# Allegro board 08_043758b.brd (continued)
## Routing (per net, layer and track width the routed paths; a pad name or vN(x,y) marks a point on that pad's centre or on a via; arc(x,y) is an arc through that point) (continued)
UNNAMED_9_RES_I270_N1: length 3.8
  BOTTOM w0.305: Q2.1 111.05,116.33 112.03,117.31 R66.2 R67.1
UNNAMED_11_ICUSB3320C_I29_RBIAS: length 1.6
  TOP w0.127: v1(87.54,100.2) U15.24
  BOTTOM w0.127: v1(87.54,100.2) 87.54,99.69 R77.1
UNNAMED_11_ICUSB3320C_I29_REFCL: length 2.2
  TOP w0.254: U15.26 86.34,101.28 R82.1
UNNAMED_11_RES_I67_N2: length 1.5
  TOP w0.305: Y1.3 87,104.35 R82.2
USB_ID: length 30.8
  TOP w0.127: U15.23 88.73,98.86 90.31,100.44 v1(90.31,100.95) ; P2.4 v1(112.41,105.9)
  L5_SIG w0.127: v1(112.41,105.9) 111.65,106.66 101.74,106.66 100.98,105.9 100.98,104.38 98.19,101.58 90.95,101.58 v1(90.31,100.95)
USB_OTG_CPEN: length 42.5
  TOP w0.127: v1(108.73,116.44) 109.41,115.77 U16.B1 ; v1(89.3,94.85) 87.9,94.85 87.54,95.21 U15.17
  L5_SIG w0.127: v1(89.3,94.85) 89.3,96.12 89.81,96.63 89.81,100.19 89.55,100.44 89.55,101.46 90.06,101.96 98.03,101.96 100.6,104.54 100.6,106.06 101.59,107.04 103.23,107.04 105.35,109.17 105.35,115.52 106.28,116.44 v1(108.73,116.44)
USB_OTG_N: length 24.6
  TOP w0.102: L6.4 107.68,103.35 107.95,103.08 107.95,101.66 105.56,99.27 94.12,99.27 91.6,96.75 87.96,96.75 87.85,96.86 U15.19
USB_OTG_P: length 25
  TOP w0.102: L6.1 108.48,103.35 108.21,103.08 108.21,101.55 105.67,99.01 94.23,99.01 91.71,96.48 87.95,96.48 87.83,96.36 U15.18
USB_VBUS_OTG: length 32.5
  TOP w0.254: v1(91.46,100.95) 89.04,98.54 88.28,98.54 88.11,98.36 U15.22
  L5_SIG w0.508: v1(91.46,100.95) 98.44,100.95 102,104.5 v1(102,105.52) v1(102.76,105.52)
  BOTTOM w0.508: v1(102,105.52) v1(102.76,105.52) 102.76,108.48 105.41,111.13 109.39,111.13 110.34,112.09 R88.2
USR_BTN: length 67.2
  TOP w0.127: U4.B9 68.07,104.03 71.87,104.03 72.37,103.53 77.48,103.53 78.79,102.22 79.14,102.22 79.52,102.6 79.52,103.16 79.77,103.41 81.85,103.41 83.58,105.14 83.58,107.3 86.25,109.97 v1(88.03,109.97)
  TOP w0.203: v1(114.35,94.56) S1.1
  L6_SIG w0.127: v1(88.03,109.97) 91.02,109.97 94.36,106.63 94.36,100.15 97.92,96.59 97.92,95.07 98.3,94.69 99.19,94.69 100.71,93.16 108.72,93.16 109.22,93.67 113.46,93.67 v1(114.35,94.56)
  BOTTOM w0.203: R57.2 88.41,109.58 v1(88.03,109.97)
USR_LED: length 57.8
  TOP w0.102: U4.D10 v2(66.47,103.23)
  TOP w0.127: Q4.1 111.69,84.86 R75.1 v1(109.22,84.86)
  L6_SIG w0.127: v1(109.22,84.86) 99.11,84.86 93.98,89.99 93.98,94.61 87.27,101.33 86.88,101.33 84.98,103.23 82.69,103.23 81.29,101.83 78.58,101.83 78.08,102.33 77.28,102.33 76.38,103.23 76.38,103.23 67.88,103.23 67.47,102.82 66.87,102.82 v2(66.47,103.23)
VTT_0P75: length 29.8
  TOP w0.203: 48.52,124.91 U14.3
  TOP w0.889: 49.66,125.55 C79.1 50.51,126.35
  BOTTOM w0.305: R22.2 R29.2 ; R22.2 54.73,123.75 ; R22.2 55.14,124.21 ; R29.2 55.14,122.15 R18.2 ; R29.2 54.73,122.95 ; 60.03,125.15 R37.2 R31.2 ; R23.2 59.66,129.38 ; R23.2 R24.2 58.86,129.38 ; R23.2 R16.2 ; 54.63,126.76 R17.2 ; R17.2 R26.2 54.63,127.56 ; R17.2 R34.2 ; R18.2 R27.2 ; R18.2 54.73,122.15 ; R27.2 55.14,120.89 ; R27.2 54.73,121.35 ; 55.14,119.69 R20.2 ; R20.2 55.14,120.61 ; R20.2 54.73,120.15 ; R16.2 60.46,129.38 ; R16.2 R35.2 ; R39.2 R33.2 ; R39.2 62.06,129.38 ; R39.2 R35.2 ; R33.2 62.86,129.38 ; R33.2 63.32,128.97 ; 52.95,128.93 C101.1 ; C101.1 52.95,130.05 ; C101.1 53.51,129.49 ; 50.79,126.26 R43.1 51.35,126.82 ; 58.5,119.13 R28.2 ; R28.2 R30.2 ; R28.2 58.96,118.72 ; 54.63,125.95 R34.2 ; R34.2 55.04,125.49 ; R21.2 R30.2 ; R21.2 60.56,118.72 ; R21.2 R38.2 ; R30.2 59.76,118.72 ; 57.46,118.72 R19.2 ; R19.2 57.91,119.13 ; R19.2 57,119.13 ; R25.2 56.66,129.38 ; R35.2 61.26,129.38 ; 60.03,124.35 R32.2 ; 60.03,123.55 R36.2
  vias: v1(51.06,125.93) v1(51.06,125.17) v1(51.82,125.93) v1(51.82,125.17)
VTTVREF: length 79.7
  TOP w0.152: 60.56,123.05 v2(60.56,122.15)
  TOP w0.203: U14.6 45.19,125.71 45.05,125.86 44.06,125.86 C84.1
  TOP w0.305: U4.F4 v2(64.87,108.83) ; U2.M8 v2(60.56,122.15) ; U2.H1 v2(63.76,127.75)
  TOP w0.508: 54.36,130.5 54.36,125.65 55.46,124.55 59.66,124.55 60.56,123.65 60.56,123.05 ; 54.36,130.5 45.59,130.5 44.77,129.68 C81.1 43.95,126.88 C84.1 ; 54.36,130.5 56.9,130.5 57.79,129.61 62.23,129.61 63.12,130.5 v1(63.76,130.5) v2(63.76,127.75)
  BOTTOM w0.152: 65.26,109.22 65.26,110.04 64.86,110.44 64.46,110.04 64.46,109.24 64.87,108.84 v2(64.87,108.83) 65.26,109.22
  BOTTOM w0.305: C63.2 64.25,127.75 v2(63.76,127.75) ; v2(60.56,122.15) 61.04,121.66 C102.1 ; 66.46,112.14 C99.2
  BOTTOM w0.508: 64.86,110.44 65.06,110.64 65.06,111.54 65.66,112.14 66.46,112.14 66.46,112.25 71.87,117.66 71.87,128.66 71.07,129.46 66.07,129.46 65.03,130.5 v1(63.76,130.5)

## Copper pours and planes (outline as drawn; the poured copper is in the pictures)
1V8 on TOP (solid shape): 47.15,82.47 47.34,82.47 47.44,82.43 47.54,82.41 48.23,82.41 48.28,82.41 48.33,82.42 48.39,82.42 48.39,82.37 48.45,82.37 48.45,82.31 48.43,82.26 48.43,82.21 48.43,81.52 48.44,81.45 48.47,81.36 48.47,81.1 50.3,81.1 50.3,80.85 50.28,80.85 50.28,80.81 50.22,80.74 49.75,80.74 49.75,79.93 50.22,79.93 50.28,79.86 50.28,79.83 50.3,79.83 50.3,78.56 47.88,78.56 46.1,80.34 46.1,83.26 47.15,83.26
1V8 on TOP (solid shape): 25.56,82.52 25.69,82.52 25.81,82.44 25.95,82.41 26.64,82.41 26.69,82.41 26.74,82.42 26.8,82.42 26.8,82.37 26.86,82.37 26.86,82.31 26.84,82.26 26.84,82.21 26.84,81.52 26.85,81.45 26.88,81.36 26.88,81.1 28.4,81.1 28.4,81.15 28.52,81.14 28.59,81.15 28.67,81.12 28.71,81.05 28.71,80.85 28.69,80.85 28.69,80.81 28.63,80.74 28.16,80.74 28.16,79.93 28.63,79.93 28.69,79.86 28.69,79.83 28.71,79.83 28.71,78.56 27.05,78.56 24.51,81.1 24.51,83.26 25.56,83.26
1V8 on TOP: 47.88,123.01 47.88,116.02 50.3,116.02 50.3,123.01
1V8 on TOP: 93.48,108.4 89.67,108.4 89.67,102.56 93.98,102.56 93.98,107.9
1V8 on TOP: 43.18,84.91 39.88,84.91 39.88,83.39 40.39,82.88 40.39,80.97 43.18,80.97
1V8 on BOTTOM: 74.81,98.75 72.14,98.75 72.14,104.98 74.81,104.98
1V8 on BOTTOM: 91.2,102.56 93.73,102.56 93.73,107.26 91.2,107.26
1V8 on L8_PWR: 68.2,77.1 68.2,83.13 56.32,83.13 51.24,78.05 26.29,78.05 26.29,85.04 29.28,85.04 30.23,85.99 45.34,85.99 45.34,93.29 47.88,93.29 47.88,121.87 92.97,121.87 92.97,87.89 106.3,87.89 106.3,77.1
1V35 on TOP: 64.27,113.85 64.27,116.05 66.86,116.05 66.86,113.85
1V35 on TOP: 76.08,124.66 72.27,124.66 72.27,127.2 76.08,127.2
1V35 on TOP: 89.79,117.17 89.79,124.03 88.9,124.91 88.9,127.71 92.97,127.71 92.97,117.17 ; 1 cut-out
1V35 on L3_PWR: 54.68,105.67 47.25,113.11 47.25,131.39 59.47,131.39 60.82,131.14 62.17,131.39 85.67,131.39 85.67,128.22 92.02,128.22 92.02,112.98 86.94,112.98 86.94,107.26 66.11,107.26 64.21,109.17 59.63,109.17 59.63,105.67
GND on TOP: 88.14,115.52 88.14,116.66 97.67,116.66 98.05,117.04 98.94,117.04 98.94,117.8 102.24,117.8 102.24,114.63 98.94,114.63 98.94,115.26 97.79,115.26 97.73,115.33 98.79,115.33 98.79,115.74 97.47,115.74 97.47,115.52 ; 2 cut-outs
GND on TOP: outline of 86 points within 9.18,72.52 117.04,140.58 ; 52 cut-outs
GND on BOTTOM: 112.62,76.18 88.68,73.51 64.62,72.52 64.62,78.16 60.82,81.96 57.02,78.16 57.02,75.77 41.53,75.77 41.53,73.15 28.69,74.18 15.88,75.68 12.53,76.16 9.18,76.66 9.18,136.43 10.24,136.6 10.24,136.6 25.22,138.56 40.26,139.87 40.26,139.86 57.02,139.86 57.02,134.94 57.14,134 57.48,133.12 57.48,131.77 58.32,131.77 58.32,132.08 59.94,131.25 61.75,131.26 61.75,130.83 63.55,130.83 63.55,131.04 64.19,131.04 64.19,133.19 64.51,134.04 64.62,134.94 64.62,140.58 85.82,139.8 106.94,137.71 106.94,112.98 103.45,109.48 103.45,107.58 104.08,108.21 110.75,108.21 111.07,107.9 111.07,101.23 117.02,101.23 117.02,98.8 117.04,98.8 117.04,87.4 117.04,81.96 117.04,80.49 116.03,77.75 113.49,76.32 ; 73 cut-outs
GND on L2_GND: 112.62,76.18 88.68,73.51 64.62,72.52 64.62,78.16 60.82,81.96 57.02,78.16 57.02,72.56 33.03,73.78 9.18,76.66 9.18,136.43 33.03,139.32 57.02,140.54 57.02,134.94 60.82,131.14 64.62,134.94 64.62,140.58 85.82,139.8 106.94,137.71 106.94,113.11 105.67,111.84 105.67,108.21 113.47,108.21 113.61,108.08 113.61,105.99 111.07,105.99 111.07,101.23 117.04,101.23 117.04,81.96 117.04,80.49 116.03,77.75 113.49,76.32
GND on L3_PWR: 112.62,76.18 88.68,73.51 64.62,72.52 64.62,78.16 60.82,81.96 57.02,78.16 57.02,72.56 33.03,73.78 9.18,76.66 9.18,136.43 33.03,139.32 57.02,140.54 57.02,134.94 57.38,133.33 58.38,132.03 46.61,132.03 46.61,123.14 32.01,123.14 32.01,115.38 34.42,112.98 39.5,112.98 44.07,108.4 44.07,95.2 40.58,95.2 40.58,82.05 40.77,81.86 54.87,81.86 54.87,89.16 59,89.16 59,82.5 63.31,82.5 65.85,79.96 117.01,79.96 115.86,77.55 113.49,76.32
GND on L4_GND, L7_GND, L9_GND: 112.62,76.18 88.68,73.51 64.62,72.52 64.62,78.16 60.82,81.96 57.02,78.16 57.02,72.56 33.03,73.78 9.18,76.66 9.18,136.43 33.03,139.32 57.02,140.54 57.02,134.94 60.82,131.14 64.62,134.94 64.62,140.58 85.82,139.8 106.94,137.71 106.94,113.11 105.67,111.84 105.67,108.21 111.07,108.21 111.07,101.23 117.04,101.23 117.04,81.96 117.04,80.49 116.03,77.75 113.49,76.32
GND on L5_SIG: 112.62,76.18 88.68,73.51 64.62,72.52 64.62,78.16 60.82,81.96 57.02,78.16 57.02,72.56 33.03,73.78 9.18,76.66 9.18,136.43 33.03,139.32 57.02,140.54 57.02,134.94 60.82,131.14 64.62,134.94 64.62,140.58 85.82,139.8 106.94,137.71 106.94,116.14 105.9,116.14 105.9,111.94 105.67,111.71 105.67,109.48 104.08,107.9 104.08,106.94 111.07,106.94 111.07,101.23 117.04,101.23 117.04,87.4 117.04,80.49 116.03,77.75 113.49,76.32 ; 45 cut-outs
GND on L6_SIG: 112.62,76.18 88.68,73.51 64.62,72.52 64.62,78.16 60.82,81.96 57.02,78.16 57.02,72.56 33.03,73.78 9.18,76.66 9.18,136.43 33.03,139.32 57.02,140.54 57.02,134.94 60.82,131.14 64.62,134.94 64.62,140.58 85.82,139.8 106.94,137.71 106.94,112.98 105.67,111.71 105.67,108.21 110.75,108.21 111.07,107.9 111.07,101.23 117.04,101.23 117.04,87.4 117.04,80.49 116.03,77.75 113.49,76.32 ; 27 cut-outs
GND on L8_PWR: 112.62,76.18 88.68,73.51 64.62,72.52 64.62,78.16 60.82,81.96 57.02,78.16 57.02,72.56 33.03,73.78 9.18,76.66 9.18,136.43 33.03,139.32 57.02,140.54 57.02,134.94 57.21,133.74 57.78,132.66 42.8,132.66 42.8,131.71 19.31,131.71 19.31,85.04 25.66,85.04 25.66,77.42 51.51,77.42 56.59,82.5 67.57,82.5 67.57,76.46 106.94,76.46 106.94,88.53 93.6,88.53 93.6,132.66 63.86,132.66 64.42,133.74 64.62,134.94 64.62,140.58 85.82,139.8 106.94,137.71 106.94,113.11 105.67,111.84 105.67,108.21 111.07,108.21 111.07,101.23 117.04,101.23 117.04,80.49 116.03,77.75 113.49,76.32
GND on L8_PWR: 28.83,93.93 28.83,112.34 44.07,112.34 44.07,120.6 47.25,120.6 47.25,93.93 44.84,93.93 38.49,100.28 35.82,100.28 35.82,93.93
PGND on TOP: 114.3,113.99 115.7,113.99 115.7,116.91 114.3,116.91
PGND on TOP: 111.26,121.36 111.26,117.17 109.6,117.17 109.6,121.36
PGND on TOP: 107.57,127.45 112.27,127.45 112.27,129.36 107.57,129.36
PGND on TOP: 111.64,114.75 111.64,115.39 109.99,115.39 109.99,110.82 111.38,110.82 111.38,114.5
PGND on L2_GND, L3_PWR, L4_GND, L7_GND, L9_GND: 111.7,101.86 111.7,105.36 114.24,105.36 114.24,108.35 113.74,108.85 106.3,108.85 106.3,111.57 107.57,112.84 107.57,137.63 110.1,137.29 112.62,136.92 113.49,136.78 116.03,135.35 117.04,132.61 117.04,129.35 117.04,127.77 116.1,127.77 115.35,127.46 115.04,126.71 115.35,125.95 116.1,125.64 117.04,125.64 117.04,123.02 116.1,123.02 115.35,122.71 115.04,121.95 115.35,121.2 116.1,120.89 117.04,120.89 117.04,109.99 116.1,109.99 115.35,109.68 115.04,108.93 115.35,108.17 116.1,107.86 117.04,107.86 117.04,105.24 116.1,105.24 115.35,104.93 115.04,104.17 115.35,103.42 116.1,103.11 117.04,103.11 117.04,101.86
PGND on L5_SIG, L6_SIG: 106.3,108.85 106.3,111.39 107.57,112.66 107.57,133.17 115.04,133.17 115.04,119.16 115.83,118.37 115.83,112.02 115.04,111.24 115.04,108.43 115.38,108.09 115.38,105.04 115.04,104.7 115.04,101.86 111.7,101.86 111.7,105.04 112.02,105.36 114.24,105.36 114.24,108.21 113.61,108.85
VCCPINT on TOP: 85.35,84.91 95.38,84.91 95.38,90.12 85.35,90.12
VCCPINT on TOP: 64.57,93.62 72.72,93.62 72.72,95.97 64.57,95.97
VCCPINT on L3_PWR: 77.09,86.94 77.09,89.8 54.87,89.8 54.87,105.04 60.27,105.04 60.27,108.53 63.94,108.53 65.85,106.63 86.94,106.63 86.94,95.83 92.33,95.83 92.33,86.94
VDD_INTERFACE on TOP: 40.52,85.54 40.52,89.1 40.64,89.23 40.64,89.85 43.18,89.85 43.18,85.54
VDD_INTERFACE on L8_PWR: 36.45,86.62 36.45,99.64 38.23,99.64 44.58,93.29 44.71,93.29 44.71,86.62
VIN on TOP: 99.32,87.83 99.32,89.35 99.19,89.48 99.19,89.79 99.57,89.79 99.62,89.84 99.62,90.24 99.42,90.24 99.19,90.01 99.19,91.01 99.83,91.01 99.83,91.64 102.62,91.64 104.14,90.12 104.14,87.83 ; 1 cut-out
VIN on TOP: 59.06,83.39 61.85,83.39 61.85,85.93 59.31,85.93 59.06,85.67
VIN on TOP: 45.6,123.64 45.6,124.28 44.45,124.28 43.95,123.77 43.95,121.87 45.09,121.87 45.47,122.25 45.47,123.52 ; 1 cut-out
VIN on TOP: 100.46,118.12 98.87,118.12 98.05,118.95 98.05,124.41 100.21,124.41 100.46,124.15 ; 1 cut-out
VIN on TOP: 100.59,111.83 100.59,107.64 98.43,107.64 98.43,112.09 97.92,112.6 97.92,113.23 98.94,114.25 99.95,114.25 99.95,112.47 ; 1 cut-out
VIN on TOP: 88.27,129.23 88.27,131.9 93.35,131.9 93.35,131.39 95.25,131.39 95.63,131.01 95.63,129.23
VIN on L3_PWR: 66.11,80.59 63.57,83.13 59.63,83.13 59.63,89.16 76.46,89.16 76.46,86.31 92.97,86.31 92.97,96.47 87.57,96.47 87.57,112.34 92.65,112.34 92.65,128.85 86.3,128.85 86.3,139.76 96.63,138.89 106.94,137.71 106.94,113.11 105.67,111.84 105.67,108.21 111.07,108.21 111.07,101.23 117.04,101.23 117.04,80.59
VIN on L8_PWR: 43.44,121.23 43.44,132.03 58.38,132.03 60.82,131.14 63.25,132.03 92.97,132.03 92.97,122.5 47.25,122.5 47.25,121.23
VIN_5V_USB on TOP: 108.97,124.79 108.72,125.04 108.72,126.69 110.11,126.69 110.62,126.18 110.62,125.92 110.1,125.92 110.1,124.8 110.62,124.8 110.62,124.79
VIN_5V_USB on TOP: 108.21,110.82 108.21,110.85 108.84,110.85 108.84,111.26 108.21,111.26 108.21,113.36 109.48,113.36 109.48,110.94 109.35,110.82
VIN_5V_USB on TOP: 107.57,130.5 111.51,130.5 111.51,133.17 107.57,133.17
VIN_5V_USB on L8_PWR: 107.57,111.39 107.57,137.63 109.8,137.33 112.02,137.01 112.02,127.58 110.43,127.58 110.43,111.39
VIN_5V_USB_DATA on TOP: 108.21,108.91 108.21,110.07 109.18,110.07 109.18,110.15 109.19,110.15 109.19,110.55 108.21,110.55 108.21,110.56 109.35,110.56 109.86,110.06 110.87,110.06 112.34,108.59 112.34,108.02 111.89,108.02 111,108.91
VIN_5V_USB_DATA on BOTTOM: 108.21,110.44 111,110.44 111,108.85 108.21,108.85
VIN_5V_USB_POWER on TOP: 110.75,124.79 113.78,124.79 113.78,125.82 112.76,125.82 112.51,126.07 112.51,126.69 111.26,126.69 110.75,126.18 ; 1 cut-out
VIN_5V_USB_POWER on TOP: 111.89,115.64 113.29,115.64 113.29,116.91 111.89,116.91
VIN_5V_USB_POWER on L8_PWR: 111.07,114.88 111.07,126.95 114.56,126.95 114.56,114.88
(no net) on TOP: 24.51,83.89 24.51,88.21 30.61,88.21 30.61,86.94 28.96,86.94 28.83,86.81 28.83,86.43 26.93,86.43 26.93,86.13 28.83,86.13 28.83,85.29 28.71,85.16 26.8,85.16 26.8,83.89 25.71,83.89 25.71,84.91 25.86,84.91 25.86,85.06 25.56,85.06 25.56,83.89
(no net) on TOP: 47.88,78.56 46.1,80.34 46.1,83.64 48.39,83.64 48.39,82.37 50.3,82.37 50.3,81.51 48.47,81.51 48.47,81.1 50.3,81.1 50.3,78.56 ; 1 cut-out
(no net) on TOP: 28.71,82.37 26.8,82.37 26.8,83.64 24.51,83.64 24.51,81.1 27.05,78.56 28.71,78.56 ; 2 cut-outs
(no net) on TOP: 46.1,83.89 46.1,88.21 50.68,88.21 51.06,88.59 52.33,88.59 52.33,87.07 50.68,87.07 50.42,86.81 50.42,86.43 48.52,86.43 48.52,86.23 50.42,86.23 50.42,85.29 50.3,85.16 48.39,85.16 48.39,83.89 47.45,83.89 47.45,85.06 47.15,85.06 47.15,83.89
1P3_SUPPLY_A on TOP (solid shape): 50.81,88.34 50.92,88.36 50.98,88.26 51.37,87.58 52.16,87.67 52.27,87.69 52.33,87.6 52.33,87.07 50.68,87.07 50.42,86.81 50.42,86.43 48.52,86.43 48.52,86.25 48.45,86.14 48.43,86.01 48.43,85.32 48.43,85.27 48.45,85.22 48.45,85.16 48.39,85.16 48.39,85.11 48.33,85.11 48.28,85.12 48.23,85.12 47.54,85.12 47.44,85.11 47.34,85.06 47.15,85.06 47.15,83.89 46.1,83.89 46.1,85.53 47.01,85.53 47.01,86.83 46.1,86.83 46.1,88.21 46.6,88.21 46.6,87.31 47.9,87.31 47.9,88.21 48.26,88.21 48.26,88.2 48.3,88.2 48.33,88.17 48.36,88.13 48.36,87.66 49.18,87.66 49.18,88.13 49.21,88.17 49.25,88.2 49.28,88.2 49.28,88.21 49.53,88.21 49.53,88.2 49.57,88.2 49.6,88.17 49.63,88.13 49.63,87.66 50.45,87.66 50.45,88.13 50.48,88.17 50.52,88.2 50.55,88.2 50.55,88.21 50.68,88.21
1P3_SUPPLY_A on L3_PWR: 41.22,82.5 41.22,94.56 44.71,94.56 44.71,108.66 39.76,113.61 34.68,113.61 32.64,115.65 32.64,122.5 46.61,122.5 46.61,112.84 54.23,105.22 54.23,82.5
1P3_SUPPLY_B on TOP (solid shape): 25.01,87.31 26.31,87.31 26.31,88.21 26.67,88.21 26.67,88.2 26.71,88.2 26.74,88.17 26.77,88.13 26.77,87.66 27.59,87.66 27.59,88.13 27.62,88.17 27.66,88.2 27.69,88.2 27.69,88.21 27.94,88.21 27.94,88.2 27.98,88.2 28.01,88.17 28.04,88.13 28.04,87.66 28.86,87.66 28.86,88.13 28.89,88.17 28.93,88.2 28.96,88.2 28.96,88.21 29.43,88.21 29.51,88.17 29.53,88.09 29.77,87.41 30.47,87.29 30.57,87.28 30.61,87.19 30.61,86.94 28.96,86.94 28.83,86.81 28.83,86.43 26.93,86.43 26.93,86.26 26.87,86.14 26.84,86.01 26.84,85.32 26.84,85.27 26.86,85.22 26.86,85.16 26.8,85.16 26.8,85.11 26.74,85.11 26.69,85.12 26.64,85.12 25.95,85.12 25.85,85.11 25.75,85.06 25.56,85.06 25.56,83.89 24.51,83.89 24.51,85.53 25.42,85.53 25.42,86.83 24.51,86.83 24.51,88.21 25.01,88.21
1P3_SUPPLY_B on L8_PWR: 19.94,85.67 19.94,131.07 42.8,131.07 42.8,120.6 43.44,120.6 43.44,112.98 28.2,112.98 28.2,93.29 35.82,93.29 35.82,86.62 29.97,86.62 29.02,85.67
1P8V_CLK on TOP: 53.09,87.07 55.76,87.07 56.01,87.32 57.03,87.32 57.03,88.21 56.52,88.72 53.09,88.72
1P8V_CLK on L6_SIG: 34.38,84.08 49.86,84.08 51.19,85.42 55.86,85.42 55.86,90.75 33.48,90.75 33.48,84.98
SYNC on TOP: 96.02,84.91 98.81,84.91 98.81,91.01 96.78,91.01 96.02,90.24 ; 1 cut-out
TX1A_N on TOP (solid shape): 31.05,101.95 31.26,101.79 31.52,101.73 31.64,101.73 31.64,100.88 29.63,100.88 29.02,101.49 29.02,101.95
TX1A_P on TOP (solid shape): 31.64,102.57 31.31,102.57 31.09,102.35 29.02,102.35 29.02,102.81 29.63,103.42 31.64,103.42
UNNAMED_2_ADM7160V2_I254_VIN on TOP: 58.8,87.45 59.57,87.45 60.07,86.94 61.85,86.94 61.85,89.74 59.06,89.74 59.06,88.59 58.8,88.34
UNNAMED_2_ADP2164_I29_EN on TOP: 99.83,91.89 103,91.89 103,93.04 99.83,93.04 ; 1 cut-out
UNNAMED_4_ICTPS51206_I44_VLDOIN on TOP: 47.12,124.41 48.14,124.41 48.39,124.15 48.39,123.52 50.17,123.52 50.17,124.28 49.84,124.61 47.12,124.61
UNNAMED_9_ADM1177_I23_SENSE on TOP: 96.78,135.07 96.78,130.38 100.21,130.38 100.21,135.07
UNNAMED_9_ADM1177_I23_VCC on TOP: 101.1,130.38 106.81,130.38 106.81,135.33 101.1,135.33
UNNAMED_9_ADP198_I329_VOUT on TOP: 111.89,115.39 111.89,110.82 113.29,110.82 113.29,114.63 112.53,115.39
UNNAMED_9_ADP198_I329_VOUT on BOTTOM: 111.51,108.85 113.8,108.85 113.8,113.36 111.89,113.36 111.89,111.33 111.51,111.33
UNNAMED_9_ADP2114_I196_SW1 on TOP: 98.62,115.01 98.62,114.44 96.9,112.72 93.98,112.72 93.98,115.01 ; 1 cut-out
UNNAMED_9_ADP2114_I196_SW3 on TOP: 93.98,117.17 93.98,120.98 95.38,120.98 95.38,119.45 96.99,119.45 98.32,118.12 98.62,118.12 98.62,117.17 97.98,117.17 97.98,118.22 97.47,118.22 97.47,117.17
UNNAMED_9_CAP_I163_N1 on TOP: 89.79,108.79 93.6,108.79 93.6,110.94 93.09,110.94 92.84,111.2 92.84,115.01 89.79,115.01
UNNAMED_9_CN5P3SHLD_I255_N6 on TOP: 114.05,101.86 114.05,104.34 114.56,104.85 114.56,108.4 114.3,108.66 114.3,113.42 117.04,113.42 117.04,109.99 116.1,109.99 115.35,109.67 115.04,108.93 115.35,108.17 116.1,107.86 117.04,107.86 117.04,105.23 116.1,105.23 115.35,104.92 115.04,104.17 115.35,103.42 116.1,103.11 117.03,103.11 117.03,102.05 116.84,101.86
UNNAMED_9_CN5P3SHLD_I256_N6 on TOP: 112.27,118.18 112.27,119.96 114.05,121.74 114.05,122.12 114.54,122.61 114.54,126.84 114.03,127.34 114.03,128.98 117.04,128.98 117.04,127.77 116.1,127.77 115.35,127.45 115.04,126.71 115.35,125.95 116.1,125.64 117.04,125.64 117.04,123.01 116.1,123.01 115.35,122.7 115.04,121.95 115.35,121.2 116.1,120.89 117.04,120.89 117.04,119.94 117.01,119.94 117.01,118.18
VTT_0P75 on TOP: 48.14,124.81 52.07,124.81 52.07,126.82 48.77,126.82 48.77,125.3 48.49,125.02 48.14,125.02
VTT_0P75 on BOTTOM: 52.71,130.5 52.71,127.58 52.2,127.07 50.55,127.07 50.55,124.76 51.15,124.15 52.85,124.15 53.25,123.75 53.25,117.95 60.76,117.95 60.76,119.35 55.26,119.35 55.26,123.9 57.61,123.9 58.24,123.26 60.71,123.26 60.71,125.75 58.46,125.75 57.76,125.05 56.89,125.05 55.36,126.59 55.36,127.96 55.38,127.96 55.38,128.98 58.17,128.98 58.42,128.72 63.63,128.72 63.63,129.74 62.87,130.5 58.93,130.5 58.04,131.39 53.6,131.39

Small or netless copper shapes (teardrops, artwork), in the pictures only: 2 on TOP, 1 on L3_PWR

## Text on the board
BOTTOM: SECONDARY SIDE
TOP: ADALM-PLUTO | PRIMARY SIDE | 08-043758 REV B Z
Ref Des/Assembly Top: K | A | ASSEMBLY NOTES: | 1. DS1 AND DS2 ARE RIGHT ANGLE LEDs
Ref Des/Silkscreen Top: K | A
DIMENSION: " " | SEE DETAIL A | -0.076 | -0.242 | 2.486 | 2.320 | 2.240 | .004 | 0 | 4.297 | R13.599 | 1.932 | 1.899 | 1.745 | 1.712 | 1.232 | 1.199 | 1.045 | 1.012 | R.191 | 0.0330 | (2PLCS) | 0.0165 | 0.0395 | 0.0790 | RADIUS | FULL | SCALE: NONE | DETAIL A | 0.1870 | EDGE | PCB | REF | ARRAY DIMENSIONS | BOARD DIMENSIONS | x2 | FIDUCIAL | TOOLING HOLE (4X) | MOLEX47590-0001_CUTOUT-DETAIL | DIA MAX | -1.074 | .860 | .984 | 1.109 | 3.223 | 2.730
PAGE_OUTLINE: B | AS PER ECR-064863 | 22NOV16 | MBANCISOR | CUSTOMER EVAL BOARD Z
User.15: PREPREG 2.98MILS | PREPREG 2.9MILS | CORE 3MILS | NOTE: ALL IMPEDANCE TOLERANCE +/-10% | LAYER | L1 | L5 | L6 | L10 | SE = SINGLE ENDED, DP = DIFFERENTIAL PAIR | 100 OHMS DP | IMPEDANCE | 50 OHMS SE | 40 OHMS SE | 90 OHMS DP | 80 OHMS DP | REFERENCE | L4,L7 | L2 | L4 | L9 | LINE WIDTH | 19MILS | 6.5MILS | 4MILS | 9MILS | 4.5MILS | 5.5MILS | 5MILS | SPACE | 7MILS | 6MILS | N/A | IMPEDANCE TABLE
User.17: L2 GND | 08-      -07
User.18: L3 PWR | 08-      -08
User.19: L4 GND | 08-      -09
User.20: L5 SIG | 08-      -10
User.22: L6 SIG | 08-      -11
User.23: L7 GND | 08-      -12
User.24: L8 PWR | 08-      -13
User.25: L9 GND | 08-      -14
User.45: FIGURE | SIZE | 8.0 | 10.0 | 20.0 | 28.0 | 45.0 | 25.0 | 50.0 | 90.0 | 126.0 | 34.0x26.0 | 51.0x24.0 | FINISHED HOLES IN MILS | ALL UNITS ARE IN MILS | PLATED | NON-PLATED | QTY | 592 | 784 | 15 | 10 | 22 | 18 | 2 | 12 | 1 | 8 | 4 | TOLERANCE/NOTES
